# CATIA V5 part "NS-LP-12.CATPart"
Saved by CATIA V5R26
Part number: NS-LP-12
Bounding box of the stored display mesh (mm): x -6.991 to 110, y -60 to 10, z -7 to 7
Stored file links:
  Y:\業務部\坪井宗男\KHI\KHI治工具標準部品\Lピン\CATIAデータ\NS-LP-12.CATPart
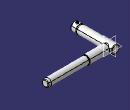
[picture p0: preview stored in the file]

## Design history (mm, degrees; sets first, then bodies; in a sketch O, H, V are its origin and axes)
Body1 (main body)
  Solid1: solid without history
